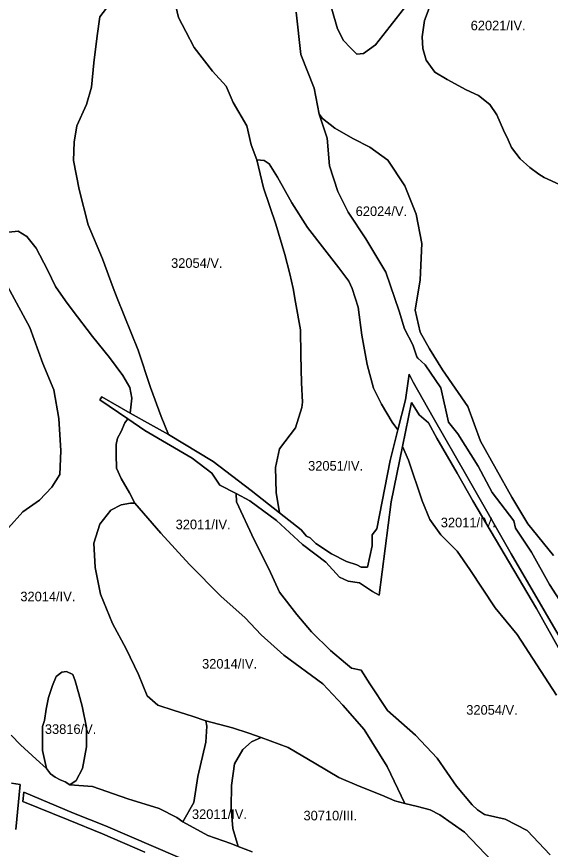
# Model space of a CAD drawing. Extents: x -521621 to -516761, y -1190184 to -1184927.
# Drawn here: x -520083 to -519249, y -1189393 to -1188092 of the extents above; entities that cross this region are included whole.
import ezdxf

# ---------------------------------------------------------------- set-up
doc = ezdxf.new("R2010")
doc.units = 0
doc.layers.add('BPEJ_s', color=7, linetype='Continuous')

msp = doc.modelspace()

# ---------------------------------------------------------------- linework, layer by layer
at = {"layer": 'BPEJ_s'}
for p, q in [((-519829.9, -1188093.4), (-519836.9, -1188064.6)), ((-519937.2, -1188072.4), (-519952.9, -1188092.5)), ((-519952.9, -1188092.5), (-519957.3, -1188122.2)), ((-519818.5, -1188115.2), (-519829.9, -1188093.4)), ((-519646.4, -1188085.3), (-519639.1, -1188151.4)), ((-519957.3, -1188122.2), (-519962.5, -1188164.1)), ((-519805.5, -1188140.5), (-519818.5, -1188115.2)), ((-519776.7, -1188177.2), (-519805.5, -1188140.5)), ((-519639.1, -1188151.4), (-519618.2, -1188203.7)), ((-519962.5, -1188164.1), (-519966, -1188202.5)), ((-519755.7, -1188200.8), (-519776.7, -1188177.2)), ((-519744.4, -1188226.1), (-519755.7, -1188200.8)), ((-519966, -1188202.5), (-519973.9, -1188229.6)), ((-519618.2, -1188203.7), (-519610.2, -1188244.8)), ((-519723.4, -1188262.8), (-519744.4, -1188226.1)), ((-519973.9, -1188229.6), (-519988.7, -1188262.8)), ((-519610.2, -1188244.8), (-519598.1, -1188281.8)), ((-519988.7, -1188262.8), (-519993.1, -1188288.1)), ((-519716.5, -1188292.4), (-519723.4, -1188262.8)), ((-519993.1, -1188288.1), (-519993.9, -1188316.9)), ((-519707.7, -1188316), (-519716.5, -1188292.4)), ((-519598.1, -1188281.8), (-519594.1, -1188325.3)), ((-519993.9, -1188316.9), (-519985.2, -1188362.3)), ((-519696.4, -1188316.9), (-519707.7, -1188316)), ((-519688.5, -1188322.1), (-519696.4, -1188316.9)), ((-519675.4, -1188343.1), (-519688.5, -1188322.1)), ((-519594.1, -1188325.3), (-519581.2, -1188365.6)), ((-519652.8, -1188383.2), (-519675.4, -1188343.1)), ((-519985.2, -1188362.3), (-519971.2, -1188417.3)), ((-519581.2, -1188365.6), (-519565.1, -1188397.8)), ((-519628.3, -1188421.7), (-519652.8, -1188383.2)), ((-519565.1, -1188397.8), (-519537.7, -1188439.6)), ((-519971.2, -1188417.3), (-519948.6, -1188470.5)), ((-519601.3, -1188456.6), (-519628.3, -1188421.7)), ((-520080.5, -1188427.6), (-520094.8, -1188429.1)), ((-520066.9, -1188435.9), (-520080.5, -1188427.6)), ((-520052.5, -1188454), (-520066.9, -1188435.9)), ((-519537.7, -1188439.6), (-519506.3, -1188491.2)), ((-520034.4, -1188488), (-520052.5, -1188454)), ((-519579.5, -1188484.5), (-519601.3, -1188456.6)), ((-519948.6, -1188470.5), (-519932.2, -1188515.8)), ((-520022.3, -1188513.7), (-520034.4, -1188488)), ((-519563.8, -1188505.5), (-519579.5, -1188484.5)), ((-519506.3, -1188491.2), (-519485.4, -1188552.4)), ((-520006.4, -1188536.4), (-520022.3, -1188513.7)), ((-519558.9, -1188516.7), (-519563.8, -1188505.5)), ((-519932.2, -1188515.8), (-519926, -1188531.8)), ((-519549.6, -1188546.1), (-519558.9, -1188516.7)), ((-519996.2, -1188550.5), (-520006.4, -1188536.4)), ((-519926, -1188531.8), (-519893.1, -1188613.1)), ((-519964.2, -1188591.8), (-519996.2, -1188550.5)), ((-519543.9, -1188590), (-519549.6, -1188546.1)), ((-519485.4, -1188552.4), (-519477.2, -1188580.2)), ((-519937.6, -1188624.7), (-519964.2, -1188591.8)), ((-519535.2, -1188635.8), (-519543.9, -1188590)), ((-519477.2, -1188580.2), (-519464, -1188605)), ((-519464, -1188605), (-519458, -1188623.6)), ((-519893.1, -1188613.1), (-519873.6, -1188671.4)), ((-519917.1, -1188652.7), (-519937.6, -1188624.7)), ((-519458, -1188623.6), (-519456, -1188625.9)), ((-519456, -1188625.9), (-519444.6, -1188636.2)), ((-519525.4, -1188672.5), (-519535.2, -1188635.8)), ((-519444.6, -1188636.2), (-519420.4, -1188672.1)), ((-519906, -1188671.8), (-519917.1, -1188652.7)), ((-519469.7, -1188650.7), (-519475.5, -1188690.8)), ((-519463.4, -1188663.2), (-519469.7, -1188650.7)), ((-519432.2, -1188718.3), (-519463.4, -1188663.2)), ((-519902.9, -1188688.2), (-519906, -1188671.8)), ((-519873.6, -1188671.4), (-519857.2, -1188716.7)), ((-519513, -1188697.7), (-519525.4, -1188672.5)), ((-519420.4, -1188672.1), (-519408.6, -1188725.7)), ((-519905.3, -1188711.5), (-519902.9, -1188688.2)), ((-519475.5, -1188690.8), (-519487.6, -1188738)), ((-519496.5, -1188725.6), (-519513, -1188697.7)), ((-519873.7, -1188729.6), (-519905.3, -1188711.5)), ((-519857.2, -1188716.7), (-519845.8, -1188745.1)), ((-519379.9, -1188810), (-519432.2, -1188718.3)), ((-519845.8, -1188745.1), (-519873.7, -1188729.6)), ((-519487.6, -1188738), (-519496.5, -1188725.6)), ((-519408.6, -1188725.7), (-519393.7, -1188743.9)), ((-519393.7, -1188743.9), (-519361.8, -1188794.8)), ((-519361.8, -1188794.8), (-519339.9, -1188835.9)), ((-519310.7, -1188931.3), (-519379.9, -1188810)), ((-519339.9, -1188835.9), (-519306.2, -1188880.2)), ((-519306.2, -1188880.2), (-519303.9, -1188891.3)), ((-519303.9, -1188891.3), (-519278.8, -1188929)), ((-519278.8, -1188929), (-519250.7, -1188979.3)), ((-519204.4, -1189113.9), (-519310.7, -1188931.3)), ((-519250.7, -1188979.3), (-519219.5, -1189028.1))]:
    msp.add_line(p, q, dxfattribs=at)
for points in [[(-519836.9, -1188064.6), (-519829.9, -1188093.4), (-519818.5, -1188115.2), (-519805.5, -1188140.5), (-519776.7, -1188177.2), (-519755.7, -1188200.8), (-519744.4, -1188226.1), (-519723.4, -1188262.8), (-519716.5, -1188292.4), (-519707.7, -1188316), (-519697.3, -1188359.7), (-519678.1, -1188416.4), (-519664.1, -1188463.6), (-519656.2, -1188494.1), (-519651.1, -1188517.2), (-519647.5, -1188538.4), (-519639.3, -1188581.7), (-519638.8, -1188620.9), (-519637.7, -1188664.2), (-519636.4, -1188694.5), (-519637.3, -1188702.9), (-519647.1, -1188734.5), (-519672.4, -1188767.3), (-519678.6, -1188796.7), (-519677.3, -1188835.8), (-519672.1, -1188867.5), (-519716.5, -1188832.7), (-519775.8, -1188787.5), (-519845.8, -1188745.1), (-519857.2, -1188716.7), (-519873.6, -1188671.4), (-519893.1, -1188613.1), (-519926, -1188531.8), (-519932.2, -1188515.8), (-519948.6, -1188470.5), (-519971.2, -1188417.3), (-519985.2, -1188362.3), (-519993.9, -1188316.9), (-519993.1, -1188288.1), (-519988.7, -1188262.8), (-519973.9, -1188229.6), (-519966, -1188202.5), (-519962.5, -1188164.1), (-519957.3, -1188122.2), (-519952.9, -1188092.5), (-519937.2, -1188072.4)], [(-519475.2, -1188075.8), (-519499.2, -1188107), (-519522.3, -1188136.3), (-519541, -1188149.7), (-519551.6, -1188150.6), (-519561.4, -1188140.8), (-519572.1, -1188129.2), (-519581.9, -1188111.4), (-519590.8, -1188080.3)], [(-519590.8, -1188080.3), (-519581.9, -1188111.4), (-519572.1, -1188129.2), (-519561.4, -1188140.8), (-519551.6, -1188150.6), (-519541, -1188149.7), (-519522.3, -1188136.3), (-519499.2, -1188107), (-519475.2, -1188075.8)], [(-519234.9, -1188354.2), (-519258.9, -1188343.4), (-519267.2, -1188338.2), (-519281.2, -1188328.1), (-519296.6, -1188314.2), (-519309.9, -1188296.5), (-519315.2, -1188284.9), (-519322.3, -1188269.7), (-519333, -1188245.7), (-519343.6, -1188229.7), (-519361.4, -1188215.5), (-519381, -1188206.6), (-519410.3, -1188190.6), (-519429.9, -1188179), (-519443.2, -1188160.3), (-519448.5, -1188141.7), (-519449.4, -1188123.9), (-519445.9, -1188098.1), (-519437, -1188075)], [(-519437, -1188075), (-519445.9, -1188098.1), (-519449.4, -1188123.9), (-519448.5, -1188141.7), (-519443.2, -1188160.3), (-519429.9, -1188179), (-519410.3, -1188190.6), (-519381, -1188206.6), (-519361.4, -1188215.5), (-519343.6, -1188229.7), (-519333, -1188245.7), (-519322.3, -1188269.7), (-519315.2, -1188284.9), (-519309.9, -1188296.5), (-519296.6, -1188314.2), (-519281.2, -1188328.1), (-519267.2, -1188338.2), (-519258.9, -1188343.4), (-519234.9, -1188354.2)], [(-519244.6, -1188934), (-519284.3, -1188884.8), (-519309.2, -1188843.1), (-519358.3, -1188755.3), (-519378.4, -1188701.4), (-519417.8, -1188644.2), (-519437.9, -1188611.2), (-519452.4, -1188585.4), (-519460.5, -1188550.8), (-519452.4, -1188503.3), (-519450, -1188446.9), (-519458.9, -1188401), (-519476.6, -1188356.7), (-519503.1, -1188316.4), (-519531.3, -1188296.3), (-519557.8, -1188282.6), (-519586, -1188266.5), (-519605.3, -1188251.2), (-519610.2, -1188244.8), (-519618.2, -1188203.7), (-519639.1, -1188151.4), (-519646.4, -1188085.3)], [(-519219.5, -1189028.1), (-519250.7, -1188979.3), (-519278.8, -1188929), (-519303.9, -1188891.3), (-519306.2, -1188880.2), (-519339.9, -1188835.9), (-519361.8, -1188794.8), (-519393.7, -1188743.9), (-519408.6, -1188725.7), (-519420.4, -1188672.1), (-519444.6, -1188636.2), (-519456, -1188625.9), (-519458, -1188623.6), (-519464, -1188605), (-519477.2, -1188580.2), (-519485.4, -1188552.4), (-519506.3, -1188491.2), (-519537.7, -1188439.6), (-519565.1, -1188397.8), (-519581.2, -1188365.6), (-519594.1, -1188325.3), (-519598.1, -1188281.8), (-519610.2, -1188244.8), (-519605.3, -1188251.2), (-519586, -1188266.5), (-519557.8, -1188282.6), (-519531.3, -1188296.3), (-519503.1, -1188316.4), (-519476.6, -1188356.7), (-519458.9, -1188401), (-519450, -1188446.9), (-519452.4, -1188503.3), (-519460.5, -1188550.8), (-519452.4, -1188585.4), (-519437.9, -1188611.2), (-519417.8, -1188644.2), (-519378.4, -1188701.4), (-519358.3, -1188755.3), (-519309.2, -1188843.1), (-519284.3, -1188884.8), (-519244.6, -1188934)], [(-520094.8, -1188429.1), (-520080.5, -1188427.6), (-520066.9, -1188435.9), (-520052.5, -1188454), (-520034.4, -1188488), (-520022.3, -1188513.7), (-520006.4, -1188536.4), (-519996.2, -1188550.5), (-519964.2, -1188591.8), (-519937.6, -1188624.7), (-519917.1, -1188652.7), (-519906, -1188671.8), (-519902.9, -1188688.2), (-519905.3, -1188711.5), (-519949.6, -1188686), (-519952.8, -1188691.1), (-519909.2, -1188720.8), (-519913.6, -1188726.9), (-519919.8, -1188740.2), (-519925.1, -1188750.9), (-519927.6, -1188760.8), (-519927.6, -1188776.4), (-519926.9, -1188797.5), (-519919.4, -1188813.8), (-519906.6, -1188836.2), (-519898.4, -1188852.5), (-519905.2, -1188852.5), (-519919.4, -1188855.2), (-519935.7, -1188863.3), (-519952.7, -1188885), (-519962.2, -1188914.9), (-519960.2, -1188952.9), (-519952, -1188994.3), (-519933, -1189040.5), (-519912, -1189079.9), (-519892.3, -1189119.9), (-519878.7, -1189153.2), (-519862.5, -1189168.1), (-519836.7, -1189176.3), (-519808.9, -1189185.1), (-519787.1, -1189192.6), (-519785.8, -1189200.7), (-519787.1, -1189225.8), (-519800, -1189279.5), (-519806.1, -1189320.2), (-519823.1, -1189350.1), (-519832.6, -1189343.3), (-519860.4, -1189329.7), (-519909.3, -1189314.1), (-519964.2, -1189295.1), (-519999.5, -1189292.4), (-519990, -1189285.6), (-519979.8, -1189267.2), (-519973.7, -1189233.3), (-519973.7, -1189202.7), (-519980.5, -1189169.5), (-519985.7, -1189150.5), (-519991.3, -1189129.8), (-519995.1, -1189120.1), (-520005.1, -1189115.4), (-520012.4, -1189116.3), (-520021.1, -1189123.2), (-520026.8, -1189137), (-520033.1, -1189155.9), (-520036.8, -1189174.1), (-520039.4, -1189191.9), (-520042.6, -1189201.2), (-520042.6, -1189238.6), (-520036, -1189267.1), (-520052.4, -1189252.4), (-520076.6, -1189230.1), (-520091.5, -1189215)], [(-520095.6, -1188890.9), (-520072.9, -1188866), (-520047.2, -1188847.8), (-520027.6, -1188827.4), (-520015.5, -1188807.8), (-520014, -1188770.7), (-520017, -1188720.1), (-520024.6, -1188675.5), (-520041.9, -1188633.9), (-520062.3, -1188578), (-520100.1, -1188507.7)], [(-520100.1, -1188507.7), (-520062.3, -1188578), (-520041.9, -1188633.9), (-520024.6, -1188675.5), (-520017, -1188720.1), (-520014, -1188770.7), (-520015.5, -1188807.8), (-520027.6, -1188827.4), (-520047.2, -1188847.8), (-520072.9, -1188866), (-520095.6, -1188890.9)], [(-519209.5, -1189126.9), (-519271.1, -1189017), (-519370.1, -1188848.5), (-519394.7, -1188805.3), (-519426.8, -1188750.9), (-519439.4, -1188726.9), (-519454, -1188714.2), (-519466.3, -1188695.3), (-519480.3, -1188763.6), (-519498.1, -1188850.3), (-519516.8, -1188996.2), (-519526.9, -1188990.3), (-519547.4, -1188976.7), (-519565.1, -1188974.3), (-519578.6, -1188967.9), (-519600.1, -1188944.4), (-519636.5, -1188916.9), (-519676.9, -1188879.4), (-519718.5, -1188848.7), (-519739.9, -1188837.5), (-519765.3, -1188824.2), (-519777.8, -1188805.7), (-519808.7, -1188781.9), (-519882.5, -1188738.9), (-519909.2, -1188720.8), (-519952.8, -1188691.1), (-519949.6, -1188686), (-519905.3, -1188711.5), (-519873.7, -1188729.6), (-519845.8, -1188745.1), (-519775.8, -1188787.5), (-519716.5, -1188832.7), (-519672.1, -1188867.5), (-519638.2, -1188894), (-519630.1, -1188903.7), (-519624.6, -1188906.3), (-519615.7, -1188915.2), (-519590.9, -1188931.4), (-519567.4, -1188943.4), (-519551.6, -1188948.9), (-519544.6, -1188952.3), (-519535, -1188952.6), (-519527.4, -1188918.9), (-519527.5, -1188902.1), (-519520.2, -1188892.7), (-519499.7, -1188785.5), (-519487.6, -1188738), (-519475.5, -1188690.8), (-519469.7, -1188650.7), (-519463.4, -1188663.2), (-519432.2, -1188718.3), (-519379.9, -1188810), (-519310.7, -1188931.3), (-519204.4, -1189113.9)], [(-519239.6, -1189152.3), (-519300.9, -1189057.7), (-519335.6, -1189016), (-519374.8, -1188956.2), (-519394.9, -1188927.5), (-519420.5, -1188901.9), (-519437.6, -1188877.7), (-519449.7, -1188848.6), (-519470.8, -1188785.2), (-519480.3, -1188763.6), (-519466.3, -1188695.3), (-519454, -1188714.2), (-519439.4, -1188726.9), (-519426.8, -1188750.9), (-519394.7, -1188805.3), (-519370.1, -1188848.5), (-519271.1, -1189017), (-519209.5, -1189126.9)], [(-519329.3, -1189423.2), (-519383.2, -1189366.6), (-519422, -1189339.1), (-519437.1, -1189331.7), (-519456.7, -1189326.3), (-519476.4, -1189321.5), (-519504.2, -1189263.8), (-519540.2, -1189206.1), (-519573.4, -1189168.1), (-519604.6, -1189134.9), (-519665.7, -1189090.1), (-519701, -1189058.1), (-519726.1, -1189031.7), (-519764.1, -1188997.7), (-519812.9, -1188948.2), (-519857.7, -1188899.3), (-519898.4, -1188852.5), (-519906.6, -1188836.2), (-519919.4, -1188813.8), (-519926.9, -1188797.5), (-519927.6, -1188776.4), (-519927.6, -1188760.8), (-519925.1, -1188750.9), (-519919.8, -1188740.2), (-519913.6, -1188726.9), (-519909.2, -1188720.8), (-519882.5, -1188738.9), (-519808.7, -1188781.9), (-519777.8, -1188805.7), (-519765.3, -1188824.2), (-519739.9, -1188837.5), (-519739.4, -1188850.1), (-519711.8, -1188909.5), (-519688.8, -1188955), (-519672.5, -1188991.6), (-519645.3, -1189026.2), (-519622.3, -1189053.4), (-519592.4, -1189082.6), (-519569.4, -1189102.3), (-519559.9, -1189110.4), (-519544.9, -1189113.1), (-519531.4, -1189134.9), (-519503.6, -1189176.3), (-519460.1, -1189215), (-519426.2, -1189250.9), (-519395.7, -1189294.4), (-519371.3, -1189323.6), (-519363.1, -1189331.7), (-519352, -1189338.6), (-519319.6, -1189346.1), (-519285.7, -1189363.9), (-519249.6, -1189401.6)], [(-519249.6, -1189401.6), (-519285.7, -1189363.9), (-519319.6, -1189346.1), (-519352, -1189338.6), (-519363.1, -1189331.7), (-519371.3, -1189323.6), (-519395.7, -1189294.4), (-519426.2, -1189250.9), (-519460.1, -1189215), (-519503.6, -1189176.3), (-519531.4, -1189134.9), (-519544.9, -1189113.1), (-519559.9, -1189110.4), (-519569.4, -1189102.3), (-519592.4, -1189082.6), (-519622.3, -1189053.4), (-519645.3, -1189026.2), (-519672.5, -1188991.6), (-519688.8, -1188955), (-519711.8, -1188909.5), (-519739.4, -1188850.1), (-519739.9, -1188837.5), (-519718.5, -1188848.7), (-519676.9, -1188879.4), (-519636.5, -1188916.9), (-519600.1, -1188944.4), (-519578.6, -1188967.9), (-519565.1, -1188974.3), (-519547.4, -1188976.7), (-519526.9, -1188990.3), (-519516.8, -1188996.2), (-519498.1, -1188850.3), (-519480.3, -1188763.6), (-519470.8, -1188785.2), (-519449.7, -1188848.6), (-519437.6, -1188877.7), (-519420.5, -1188901.9), (-519394.9, -1188927.5), (-519374.8, -1188956.2), (-519335.6, -1189016), (-519300.9, -1189057.7), (-519239.6, -1189152.3)], [(-520091.5, -1189215), (-520076.6, -1189230.1), (-520052.4, -1189252.4), (-520036, -1189267.1), (-520029.9, -1189275.1), (-520022.9, -1189280.4), (-520014.9, -1189284.7), (-520007, -1189287.9), (-519999.5, -1189292.4), (-519964.2, -1189295.1), (-519909.3, -1189314.1), (-519860.4, -1189329.7), (-519832.6, -1189343.3), (-519823.1, -1189350.1), (-519784.4, -1189371.8), (-519748.5, -1189384), (-519736.9, -1189388.8), (-519715.2, -1189396.9)], [(-519715.2, -1189396.9), (-519736.9, -1189388.8), (-519745.1, -1189360.9), (-519747.8, -1189327.7), (-519747.1, -1189293.7), (-519742.4, -1189259.8), (-519729.5, -1189237.4), (-519715.9, -1189225.1), (-519701, -1189218.4), (-519658.9, -1189234), (-519615.5, -1189259.8), (-519579.5, -1189280.8), (-519547.7, -1189294.4), (-519512.4, -1189308.7), (-519492, -1189317.5), (-519476.4, -1189321.5), (-519456.7, -1189326.3), (-519437.1, -1189331.7), (-519422, -1189339.1), (-519383.2, -1189366.6), (-519329.3, -1189423.2)], [(-520083.9, -1189362.4), (-520077.5, -1189292), (-520090.6, -1189290.1)], [(-520090.6, -1189290.1), (-520077.5, -1189292), (-520083.9, -1189362.4)], [(-519882.5, -1189397.5), (-519948.9, -1189368.8), (-520002.1, -1189347.4), (-520073.1, -1189318.4), (-520071.8, -1189303.8), (-519994, -1189336.9), (-519944.2, -1189356.5), (-519794.2, -1189421.2)], [(-519794.2, -1189421.2), (-519944.2, -1189356.5), (-519994, -1189336.9), (-520071.8, -1189303.8), (-520073.1, -1189318.4), (-520002.1, -1189347.4), (-519948.9, -1189368.8), (-519882.5, -1189397.5)]]:
    msp.add_lwpolyline(points, dxfattribs=at)
for points in [[(-519707.7, -1188316), (-519696.4, -1188316.9), (-519688.5, -1188322.1), (-519675.4, -1188343.1), (-519652.8, -1188383.2), (-519628.3, -1188421.7), (-519601.3, -1188456.6), (-519579.5, -1188484.5), (-519563.8, -1188505.5), (-519558.9, -1188516.7), (-519549.6, -1188546.1), (-519543.9, -1188590), (-519535.2, -1188635.8), (-519525.4, -1188672.5), (-519513, -1188697.7), (-519496.5, -1188725.6), (-519487.6, -1188738), (-519499.7, -1188785.5), (-519520.2, -1188892.7), (-519527.5, -1188902.1), (-519527.4, -1188918.9), (-519535, -1188952.6), (-519544.6, -1188952.3), (-519551.6, -1188948.9), (-519567.4, -1188943.4), (-519590.9, -1188931.4), (-519615.7, -1188915.2), (-519624.6, -1188906.3), (-519630.1, -1188903.7), (-519638.2, -1188894), (-519672.1, -1188867.5), (-519677.3, -1188835.8), (-519678.6, -1188796.7), (-519672.4, -1188767.3), (-519647.1, -1188734.5), (-519637.3, -1188702.9), (-519636.4, -1188694.5), (-519637.7, -1188664.2), (-519638.8, -1188620.9), (-519639.3, -1188581.7), (-519647.5, -1188538.4), (-519651.1, -1188517.2), (-519656.2, -1188494.1), (-519664.1, -1188463.6), (-519678.1, -1188416.4), (-519697.3, -1188359.7)], [(-519898.4, -1188852.5), (-519857.7, -1188899.3), (-519812.9, -1188948.2), (-519764.1, -1188997.7), (-519726.1, -1189031.7), (-519701, -1189058.1), (-519665.7, -1189090.1), (-519604.6, -1189134.9), (-519573.4, -1189168.1), (-519540.2, -1189206.1), (-519504.2, -1189263.8), (-519476.4, -1189321.5), (-519492, -1189317.5), (-519512.4, -1189308.7), (-519547.7, -1189294.4), (-519579.5, -1189280.8), (-519615.5, -1189259.8), (-519658.9, -1189234), (-519701, -1189218.4), (-519720, -1189211.6), (-519745.8, -1189203.4), (-519787.1, -1189192.6), (-519808.9, -1189185.1), (-519836.7, -1189176.3), (-519862.5, -1189168.1), (-519878.7, -1189153.2), (-519892.3, -1189119.9), (-519912, -1189079.9), (-519933, -1189040.5), (-519952, -1188994.3), (-519960.2, -1188952.9), (-519962.2, -1188914.9), (-519952.7, -1188885), (-519935.7, -1188863.3), (-519919.4, -1188855.2), (-519905.2, -1188852.5)], [(-520036, -1189267.1), (-520042.6, -1189238.6), (-520042.6, -1189201.2), (-520039.4, -1189191.9), (-520036.8, -1189174.1), (-520033.1, -1189155.9), (-520026.8, -1189137), (-520021.1, -1189123.2), (-520012.4, -1189116.3), (-520005.1, -1189115.4), (-519995.1, -1189120.1), (-519991.3, -1189129.8), (-519985.7, -1189150.5), (-519980.5, -1189169.5), (-519973.7, -1189202.7), (-519973.7, -1189233.3), (-519979.8, -1189267.2), (-519990, -1189285.6), (-519999.5, -1189292.4), (-520007, -1189287.9), (-520014.9, -1189284.7), (-520022.9, -1189280.4), (-520029.9, -1189275.1)], [(-519823.1, -1189350.1), (-519806.1, -1189320.2), (-519800, -1189279.5), (-519787.1, -1189225.8), (-519785.8, -1189200.7), (-519787.1, -1189192.6), (-519745.8, -1189203.4), (-519720, -1189211.6), (-519701, -1189218.4), (-519715.9, -1189225.1), (-519729.5, -1189237.4), (-519742.4, -1189259.8), (-519747.1, -1189293.7), (-519747.8, -1189327.7), (-519745.1, -1189360.9), (-519736.9, -1189388.8), (-519748.5, -1189384), (-519784.4, -1189371.8)]]:
    msp.add_lwpolyline(points, close=True, dxfattribs=at)

# ---------------------------------------------------------------- texts
for s, p in [('62021/IV.', (-519373.7, -1188113.5)), ('62024/V.', (-519553.3, -1188403.7)), ('32054/V.', (-519841.6, -1188484.7)), ('32051/IV.', (-519627.6, -1188801.5)), ('32011/IV.', (-519834.5, -1188893.1)), ('32011/IV.', (-519420.4, -1188890.1)), ('32014/IV.', (-520077, -1189005.7)), ('32014/IV.', (-519793.2, -1189110.8)), ('32054/V.', (-519380.6, -1189182.9)), ('33816/V.', (-520038.7, -1189212.9)), ('32011/IV.', (-519809, -1189345.8)), ('30710/III.', (-519634.8, -1189348))]:
    msp.add_text(s, height=15, dxfattribs=at).set_placement(p)

doc.saveas('drawing.dxf')
